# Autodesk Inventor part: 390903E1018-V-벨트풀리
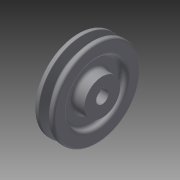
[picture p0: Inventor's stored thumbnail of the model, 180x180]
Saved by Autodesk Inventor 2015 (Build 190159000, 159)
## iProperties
Created: 2019-09
Part Number: 390903E1018-V-벨트풀리
Material: 일반
Document SubType Name: Modeling
Designer: now015
Density: 1 g/cm^3
Appearance: 기본값
Author: now015
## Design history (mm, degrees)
sketch "스케치1"
  geometry: C1 r 42.7 at (0, 0); 1 further point
  constraints: 1 centre point, 1 coincident
  dimensions: "d0" = 85.4 diameter of C1
extrude "돌출1" new body sketch "스케치1" stored distance "d1" = 19; taper "d2" = 0 deg
sketch "스케치2"
  geometry: L1 (9.5, 42.7)-(9.5, -42.7) reference; L2 (9.5, -42.7)-(-9.5, -42.7) reference; L3 (-9.5, -42.7)-(-9.5, 42.7) reference; L4 (-9.5, 42.7)-(9.5, 42.7) reference; L5 (4.877, 42.7)-(1.953, 33.7); L6 (1.953, 33.7)-(-1.953, 33.7); L7 (-1.953, 33.7)-(-4.877, 42.7); L8 (4, 40)-(-4, 40); L9 (-9.5, 42.7)-(-9.5, -42.7) reference; L10 (0, 42.7)-(0, 33.7); L11 (13.3, 0)-(-13.3, 0) reference; 1 further point
  constraints: 10 end point, 4 point on line, 2 midpoint, 1 horizontal, 1 perpendicular, 1 vertical, 1 other
  dimensions: "d3" = 36 deg angle of L7 L5; "d4" = 2.7 distance between parallel lines of L8 L4; "d5" = 6.3 distance between parallel lines of L6 L8; "d6" = 9.5 distance between parallel lines of L10 L1 (derived); "d7" = 8 distance of L8.end L8.start
revolve "회전1" sketch "스케치2" stored, may be unused: angle "d8" = 90 deg
sketch "스케치3"
  geometry: C1 r 42.7 at (0, 0) reference; C2 r 29 at (0, 0); C3 r 17.5 at (0, 0)
  constraints: 2 centre point, 2 coincident
  dimensions: "d9" = 58 diameter of C2; "d10" = 35 diameter of C3
extrude "돌출2" cut sketch "스케치3" distance "d11" = 6; taper "d12" = 0 deg
sketch "스케치4"
  geometry: C1 r 29 at (0, 0) reference; C2 r 29 at (0, 0); C3 r 17.5 at (0, 0)
  constraints: 2 centre point, 2 coincident
  dimensions: "d13" = 58 diameter of C2; "d14" = 35 diameter of C3
extrude "돌출3" cut sketch "스케치4" distance "d15" = 6; taper "d16" = 0 deg
fillet "모깎기1" dims "d17" = 3
fillet "모깎기2" dims "d18" = 3
fillet "모깎기3" dims "d19" = 3
fillet "모깎기4" dims "d20" = 3
sketch "스케치5"
  geometry: C1 r 17.5 at (0, 0) reference
extrude "돌출4" join sketch "스케치5" distance "d21" = 5; taper "d22" = 0 deg
sketch "스케치6"
  geometry: C1 r 26 at (0, 0) reference; C2 r 6 at (0, 0)
  constraints: 1 centre point, 1 coincident
  dimensions: "d23" = 12 diameter of C2
extrude "돌출5" cut sketch "스케치6" stored distance "d24" = 5; taper "d25" = 0 deg
sketch "스케치7"
  geometry: L1 (-7.8, -2)-(0, -2); L2 (0, -2)-(0, 2); L3 (0, 2)-(-7.8, 2); L4 (-7.8, 2)-(-7.8, -2); C1 r 6 at (0, 0) reference; 1 further point
  constraints: 8 end point, 2 parallel, 1 coincident, 1 horizontal, 1 midpoint, 1 perpendicular
  dimensions: "d26" = 4 distance of L3.end L1.start; "d27" = 13.8 dimension on C1 L4
extrude "돌출6" cut sketch "스케치7" stored distance "d28" = 5; taper "d29" = 0 deg
fillet "모깎기5" dims "d30" = 2
fillet "모깎기6" dims "d31" = 0.5
fillet "모깎기7" dims "d32" = 1
node "솔리드1"
node "절단 모서리 투영1"
